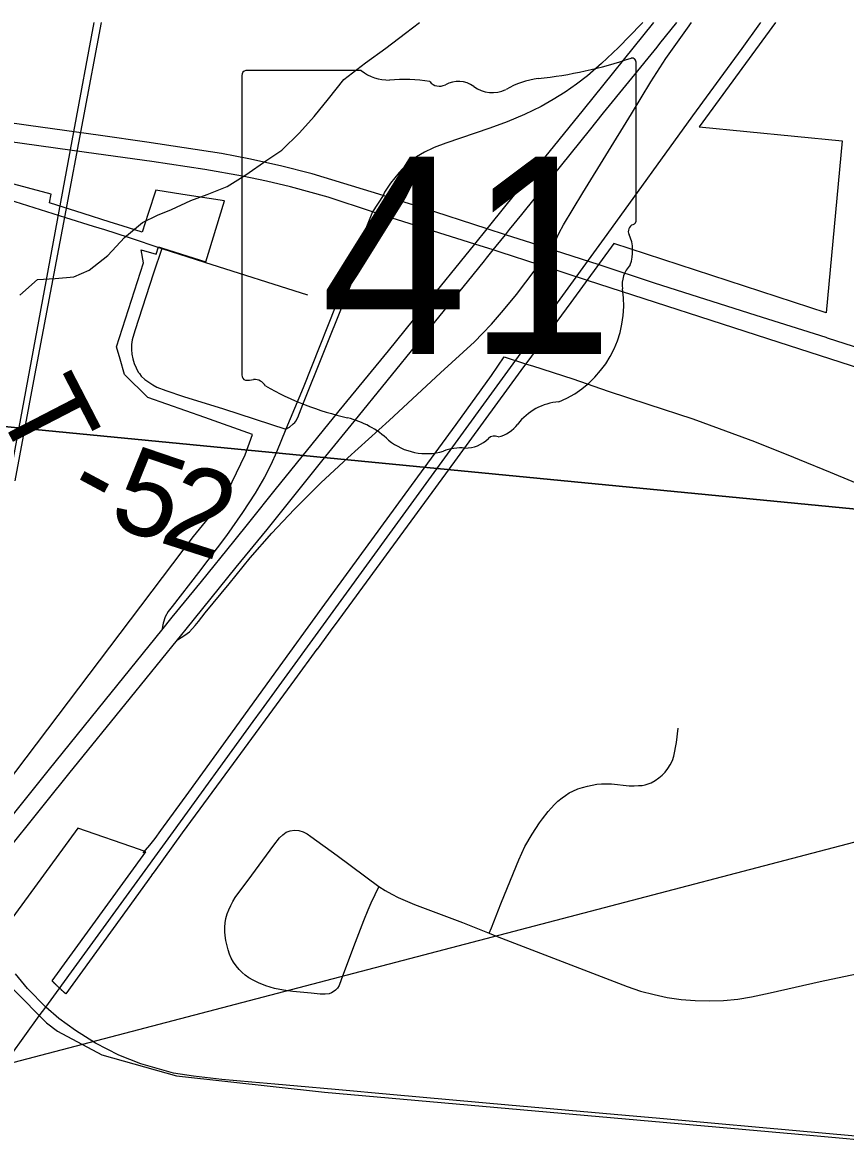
# Model space of a CAD drawing. Extents: x 0 to 34, y 0 to 22.
# Drawn here: x 7.471 to 8.022, y 20.207 to 20.958 of the extents above; entities that cross this region are included whole.
import ezdxf

# ---------------------------------------------------------------- set-up
doc = ezdxf.new("R2010")
doc.units = 0
for name, color, linetype in [('GM_X_City_Street', 7, 'Continuous'), ('GM_X_Corporation', 7, 'Continuous'), ('GM_X_Interchange_Ramps', 7, 'Continuous'), ('GM_X_Minor_River', 7, 'Continuous'), ('GM_X_Rail_Line', 7, 'Continuous'), ('GM_X_State_Location', 7, 'Continuous'), ('GM_X_State_Route', 7, 'Continuous'), ('GM_X_State_Shield', 7, 'Continuous'), ('GM_X_Township_Road', 7, 'Continuous'), ('GM_X_Township_Road_Text', 7, 'Continuous'), ('GM_X_US_Route', 7, 'Continuous'), ('SH_Text', 7, 'Continuous')]:
    doc.layers.add(name, color=color, linetype=linetype)

msp = doc.modelspace()

# ---------------------------------------------------------------- linework, layer by layer
at = {"layer": 'GM_X_City_Street'}
for points in [[(7.78356, 20.34885), (7.78502, 20.35254), (7.7914, 20.36865), (7.79975, 20.3893), (7.80337, 20.39798), (7.80737, 20.40679), (7.81218, 20.41515), (7.81462, 20.41893), (7.81711, 20.42264), (7.81915, 20.42534), (7.82296, 20.43021), (7.82493, 20.43244), (7.8271, 20.43501), (7.82947, 20.43711), (7.8323, 20.43941), (7.83451, 20.441), (7.8371, 20.4427), (7.83947, 20.44388), (7.84289, 20.44533), (7.84585, 20.44639), (7.8492, 20.44724), (7.85229, 20.44796), (7.85551, 20.44862), (7.85874, 20.44888), (7.86176, 20.44882), (7.86525, 20.44882), (7.87709, 20.4475), (7.8805, 20.44744), (7.8834, 20.44757), (7.88581, 20.44776), (7.88793, 20.44822), (7.88983, 20.44878), (7.89175, 20.44954), (7.89445, 20.45098), (7.89694, 20.4527), (7.89911, 20.45447), (7.90122, 20.45658), (7.90306, 20.45892), (7.90466, 20.46148), (7.90602, 20.46434), (7.90694, 20.46723), (7.90871, 20.4765), (7.9099, 20.48597)], [(7.70961, 20.38007), (7.70438, 20.36893), (7.70241, 20.36433), (7.69945, 20.35723), (7.69281, 20.33986), (7.68449, 20.31776), (7.68307, 20.31395), (7.68202, 20.31224), (7.68077, 20.31086), (7.67922, 20.30967), (7.678, 20.30903), (7.67643, 20.30843), (7.67387, 20.30817), (7.67038, 20.30824), (7.66433, 20.30876), (7.65212, 20.31001), (7.646, 20.31072), (7.64, 20.31198), (7.63407, 20.31373), (7.62915, 20.31573), (7.62559, 20.31751), (7.62276, 20.31915), (7.62034, 20.32086), (7.61823, 20.32263), (7.61626, 20.32474), (7.61422, 20.32718), (7.61257, 20.32947), (7.61093, 20.3323), (7.60975, 20.33493), (7.60889, 20.33783), (7.60738, 20.34394), (7.60692, 20.34736), (7.60672, 20.34984), (7.60665, 20.35287), (7.60688, 20.35587), (7.60743, 20.35885), (7.60825, 20.36176), (7.60932, 20.36461), (7.61059, 20.3674), (7.61204, 20.37009), (7.61366, 20.37267), (7.62473, 20.3877), (7.63955, 20.40777), (7.64331, 20.41265), (7.64542, 20.41472), (7.64781, 20.41636), (7.65049, 20.41742), (7.65334, 20.41781), (7.65622, 20.41755), (7.659, 20.41667), (7.66165, 20.41529), (7.66419, 20.4136), (7.68186, 20.40081), (7.70961, 20.38007)], [(7.70961, 20.38007), (7.71389, 20.37735), (7.71833, 20.37493), (7.72263, 20.37288), (7.7336, 20.36801), (7.76564, 20.35596), (7.78356, 20.34885), (7.78875, 20.34679), (7.84968, 20.32323), (7.8759, 20.31336), (7.8848, 20.31024), (7.89377, 20.30787), (7.90265, 20.306), (7.91183, 20.30462), (7.92139, 20.30392), (7.93067, 20.30363), (7.94024, 20.30383), (7.94971, 20.30481), (7.95888, 20.30639), (7.97145, 20.30907), (8.00483, 20.31659), (8.02919, 20.32164)]]:
    msp.add_lwpolyline(points, dxfattribs=at)
at = {"layer": 'GM_X_Corporation'}
for points in [[(8.11662, 20.95784), (8.08658, 20.62681), (7.08216, 20.72429), (7.10245, 20.95784)], [(7.97504, 20.95784), (7.9239, 20.88797), (8.01968, 20.8786), (8.00881, 20.76368), (7.86693, 20.8101), (7.83809, 20.77069), (7.81637, 20.74102), (7.81183, 20.73481), (7.80475, 20.72514), (7.75424, 20.65611), (7.7287, 20.62103), (7.68054, 20.55538), (7.67895, 20.5532), (7.66845, 20.53889), (7.66831, 20.53871), (7.65328, 20.51822), (7.60984, 20.45899), (7.57824, 20.41592), (7.55947, 20.39), (7.55774, 20.38761), (7.55773, 20.3876), (7.5413, 20.36498), (7.50024, 20.30844), (7.50011, 20.30855), (7.49997, 20.30867), (7.49984, 20.30879), (7.49971, 20.3089), (7.49957, 20.30902), (7.49944, 20.30914), (7.49931, 20.30926), (7.49918, 20.30938), (7.49904, 20.30949), (7.49891, 20.30961), (7.49878, 20.30973), (7.49865, 20.30985), (7.49851, 20.30997), (7.49838, 20.31009), (7.49825, 20.31021), (7.49812, 20.31033), (7.49799, 20.31044), (7.49786, 20.31056), (7.49772, 20.31068), (7.49759, 20.3108), (7.49746, 20.31092), (7.49733, 20.31104), (7.4972, 20.31116), (7.49711, 20.31124), (7.49694, 20.3114), (7.49681, 20.31152), (7.49668, 20.31165), (7.49655, 20.31177), (7.49642, 20.31189), (7.49629, 20.31201), (7.49616, 20.31213), (7.49603, 20.31225), (7.4959, 20.31237), (7.49577, 20.31249), (7.49564, 20.31262), (7.49551, 20.31274), (7.49538, 20.31286), (7.49525, 20.31298), (7.49513, 20.3131), (7.495, 20.31323), (7.49487, 20.31335), (7.49474, 20.31347), (7.49461, 20.31359), (7.49448, 20.31372), (7.49436, 20.31384), (7.49423, 20.31396), (7.4941, 20.31409), (7.49406, 20.31413), (7.49397, 20.31421), (7.49385, 20.31433), (7.49372, 20.31446), (7.49359, 20.31458), (7.49347, 20.31471), (7.49334, 20.31483), (7.49321, 20.31496), (7.49308, 20.31508), (7.49296, 20.3152), (7.49283, 20.31533), (7.49271, 20.31545), (7.49258, 20.31558), (7.49245, 20.3157), (7.49233, 20.31583), (7.4922, 20.31596), (7.49208, 20.31608), (7.49195, 20.31621), (7.49183, 20.31633), (7.4917, 20.31646), (7.49158, 20.31658), (7.49145, 20.31671), (7.49133, 20.31684), (7.4912, 20.31696), (7.49108, 20.31709), (7.55377, 20.40341), (7.54961, 20.40487), (7.50847, 20.41921), (7.46243, 20.35631)], [(7.45289, 20.43873), (7.58572, 20.61423), (7.60573, 20.63864), (7.62031, 20.66884), (7.6252, 20.68227), (7.59321, 20.69361), (7.55524, 20.70707), (7.53965, 20.72254), (7.53666, 20.73261), (7.5342, 20.74088), (7.55223, 20.79706), (7.55069, 20.80592), (7.56071, 20.80286), (7.56226, 20.80784), (7.56424, 20.80717), (7.59398, 20.79773), (7.59573, 20.80363), (7.60652, 20.83848), (7.57861, 20.84292), (7.56051, 20.8458), (7.5555, 20.83021), (7.55145, 20.81759), (7.53808, 20.82181), (7.53008, 20.82433), (7.51198, 20.83004), (7.4894, 20.83716), (7.49045, 20.84301), (7.49045, 20.84301), (7.39199, 20.86938)]]:
    msp.add_lwpolyline(points, dxfattribs=at)
msp.add_lwpolyline([(7.08216, 20.72429), (8.08658, 20.62681), (8.00052, 19.62676), (6.98964, 19.72208)], close=True, dxfattribs=at)
at = {"layer": 'GM_X_Interchange_Ramps'}
for points in [[(7.88631, 20.95784), (7.88524, 20.9567), (7.86993, 20.94121), (7.85866, 20.93048), (7.84931, 20.92227), (7.84199, 20.91649), (7.83435, 20.91115), (7.82641, 20.90624), (7.81823, 20.90176), (7.80702, 20.89636), (7.79557, 20.8915), (7.78392, 20.88714), (7.75443, 20.87725), (7.7467, 20.87422)], [(7.82467, 20.80619), (7.8262, 20.80851), (7.83037, 20.81711), (7.83321, 20.82263), (7.84605, 20.84392), (7.87873, 20.89682), (7.89153, 20.91815), (7.90174, 20.93376), (7.91605, 20.95414), (7.91879, 20.95784)], [(7.7467, 20.87422), (7.74573, 20.87384), (7.74014, 20.87114), (7.73482, 20.86794), (7.73228, 20.86615), (7.72755, 20.86213), (7.72325, 20.85763), (7.71742, 20.85034), (7.71349, 20.84434), (7.71257, 20.84209)], [(7.71257, 20.84209), (7.70551, 20.83124), (7.70097, 20.82018), (7.6865, 20.78258), (7.65897, 20.71349), (7.64755, 20.68592), (7.64128, 20.67051), (7.6374, 20.66206), (7.63315, 20.6538), (7.6269, 20.6431), (7.61847, 20.63009), (7.60775, 20.61489), (7.58913, 20.59011), (7.57137, 20.56738), (7.56882, 20.56403), (7.56676, 20.56042), (7.56534, 20.55616), (7.56462, 20.55158)], [(7.64755, 20.68592), (7.65, 20.68725), (7.65249, 20.68942), (7.65359, 20.69044), (7.65427, 20.69135), (7.65545, 20.69372), (7.65886, 20.70232), (7.67294, 20.73729), (7.69872, 20.80175), (7.70495, 20.81716), (7.70909, 20.82694), (7.71017, 20.82971)], [(7.81691, 20.79588), (7.82096, 20.80099), (7.82355, 20.80451), (7.82467, 20.80619)], [(7.77899, 20.74993), (7.78507, 20.75623), (7.79315, 20.76537), (7.80176, 20.77599), (7.81419, 20.79246), (7.81691, 20.79588)], [(7.57496, 20.54515), (7.57995, 20.54813), (7.58303, 20.55047), (7.58686, 20.55461), (7.58899, 20.55737), (7.59354, 20.56302), (7.6095, 20.58256), (7.62353, 20.59999), (7.63819, 20.61636), (7.65296, 20.63219), (7.67093, 20.64994), (7.689, 20.66674), (7.71652, 20.69181), (7.75095, 20.7236), (7.77358, 20.74433), (7.77899, 20.74993)]]:
    msp.add_lwpolyline(points, dxfattribs=at)
at = {"layer": 'GM_X_Minor_River'}
msp.add_lwpolyline([(7.46958, 20.77547), (7.48139, 20.78601), (7.49312, 20.78668), (7.50561, 20.78773), (7.51586, 20.79221), (7.52842, 20.80198), (7.53949, 20.81405), (7.55167, 20.8242), (7.56154, 20.82906), (7.57103, 20.83279), (7.58394, 20.83876), (7.59494, 20.84286), (7.60822, 20.84807), (7.62076, 20.85594), (7.63484, 20.86571), (7.64473, 20.87247), (7.65654, 20.88414), (7.66646, 20.89508), (7.67601, 20.90677), (7.68633, 20.9196), (7.70079, 20.93087), (7.71448, 20.94064), (7.72742, 20.95079), (7.73679, 20.95784)], dxfattribs=at)
at = {"layer": 'GM_X_Rail_Line'}
for points in [[(7.51897, 20.95784), (7.5055, 20.88474), (7.44147, 20.53994), (7.4238, 20.45147), (7.42156, 20.40248), (7.43115, 20.36454), (7.45915, 20.31775), (7.48232, 20.29421)], [(7.46651, 20.65131), (7.47895, 20.71815), (7.48703, 20.76062), (7.49964, 20.82769), (7.52408, 20.95784)], [(7.48694, 20.29949), (7.57229, 20.41699), (7.62563, 20.49046), (7.63117, 20.49804), (7.72066, 20.62109), (7.86237, 20.8161), (7.91983, 20.89536), (7.9405, 20.92369), (7.95265, 20.94046), (7.96452, 20.95687), (7.96523, 20.95784)], [(8.11104, 20.20593), (8.0828, 20.20842), (8.05089, 20.21113), (7.96406, 20.21905), (7.93438, 20.22168), (7.89763, 20.22503), (7.8746, 20.22707), (7.79643, 20.23387), (7.71949, 20.24089), (7.68055, 20.24438), (7.65521, 20.24672), (7.64002, 20.24795), (7.62468, 20.24921), (7.60472, 20.25118), (7.58567, 20.25323), (7.57229, 20.25534), (7.55052, 20.26159), (7.5357, 20.26734), (7.52017, 20.27544), (7.50679, 20.28377), (7.49576, 20.29186), (7.48694, 20.29949), (7.4747, 20.31195), (7.46671, 20.32172)], [(7.4536, 20.25349), (7.48255, 20.29368), (7.48694, 20.29949)], [(7.48232, 20.29421), (7.48749, 20.28896), (7.49472, 20.2834), (7.52452, 20.26748), (7.57443, 20.25347), (7.67337, 20.24253), (7.99809, 20.21388), (8.15925, 20.19925), (8.24374, 20.18913), (8.60421, 20.11965), (8.71999, 20.10062), (8.77096, 20.10215), (8.84859, 20.10474), (8.84939, 20.10462)]]:
    msp.add_lwpolyline(points, dxfattribs=at)
at = {"layer": 'GM_X_State_Route'}
for points in [[(7.962, 20.76198), (7.89404, 20.78353), (7.85705, 20.79574), (7.8271, 20.80541), (7.82467, 20.80619), (7.79439, 20.81596), (7.78215, 20.81991), (7.73818, 20.83409), (7.71637, 20.8409), (7.71257, 20.84209), (7.66507, 20.85653), (7.64403, 20.862), (7.62282, 20.86674), (7.60452, 20.8702), (7.5546, 20.87776), (7.52353, 20.8823), (7.47531, 20.88902), (7.41986, 20.89665)], [(7.81691, 20.79588), (7.79091, 20.80436), (7.78621, 20.80584), (7.77387, 20.80971), (7.71017, 20.82971), (7.70953, 20.82992), (7.70685, 20.8308), (7.70551, 20.83124), (7.6757, 20.84098), (7.6505, 20.84787), (7.63455, 20.85173), (7.6186, 20.85509), (7.59323, 20.85945), (7.55796, 20.86483), (7.51412, 20.87087), (7.46155, 20.87826)], [(8.07216, 20.7137), (8.03899, 20.72408), (7.97751, 20.74392), (7.84934, 20.78529), (7.81995, 20.79488), (7.81691, 20.79588)], [(8.00982, 20.7468), (8.0089, 20.7471), (7.962, 20.76198)], [(8.0751, 20.72589), (8.06255, 20.7298), (8.02729, 20.74124), (8.00982, 20.7468)]]:
    msp.add_lwpolyline(points, dxfattribs=at)
at = {"layer": 'GM_X_State_Shield'}
for p, q in [((7.88178, 20.82601), (7.88178, 20.93069)), ((7.61812, 20.92229), (7.61812, 20.72217)), ((7.69793, 20.92574), (7.62071, 20.92574)), ((7.88176, 20.82604), (7.88178, 20.82601))]:
    msp.add_line(p, q, dxfattribs=at)
for centre, radius, start, end in [((7.78786, 21.19857), 0.27962, 275.84447, 288.90645), ((7.87886, 20.93113), 0.00294, 351.86209, 97.738), ((7.62114, 20.92272), 0.00305, 98.1301, 188.1301), ((7.71632, 20.94897), 0.02963, 231.61951, 271.11188), ((7.82353, 20.86461), 0.05625, 97.34618, 120.76885), ((7.72614, 20.81339), 0.10636, 80.48669, 94.98827), ((7.75029, 20.92376), 0.00855, 219.79206, 297.10237), ((7.76284, 20.90063), 0.01777, 54.46668, 119.14113), ((7.78577, 20.93235), 0.02138, 233.85621, 294.82819), ((7.8811, 20.81832), 0.00454, 107.94398, 210.33697), ((7.87865, 20.82561), 0.00314, 289.60381, 7.73413), ((7.85221, 20.80509), 0.02727, 340.03296, 23.64957), ((7.8923, 20.7822), 0.01984, 136.8065, 186.92959), ((7.80352, 20.76888), 0.06994, 292.30889, 8.98584), ((7.62116, 20.72173), 0.00308, 171.95839, 258.30661), ((7.62163, 20.74221), 0.02352, 267.33899, 280.60386), ((7.62644, 20.71063), 0.00848, 29.74838, 93.27175), ((7.7335, 20.89043), 0.20192, 240.41292, 257.1985), ((7.83301, 20.66599), 0.0383, 94.40312, 142.57675), ((7.6733, 20.63227), 0.06318, 47.18416, 75.83597), ((7.78448, 20.70278), 0.0226, 282.87319, 323.27711), ((7.78705, 20.67527), 0.00601, 65.75173, 132.64842), ((7.74163, 20.70963), 0.04009, 230.70037, 286.29184), ((7.7648, 20.64044), 0.03294, 85.69512, 111.20995), ((7.76773, 20.69465), 0.02136, 268.77702, 315.54927)]:
    msp.add_arc(centre, radius, start, end, dxfattribs=at)
at = {"layer": 'GM_X_Township_Road'}
for p, q in [((7.56447, 20.80664), (7.59312, 20.79755)), ((7.59312, 20.79755), (7.66187, 20.77572))]:
    msp.add_line(p, q, dxfattribs=at)
for points in [[(7.4174, 20.85338), (7.44408, 20.84508), (7.44473, 20.84487), (7.50016, 20.82753), (7.51866, 20.82171), (7.52617, 20.81931), (7.54209, 20.8142), (7.56447, 20.80664)], [(7.56447, 20.80664), (7.55898, 20.79019), (7.54642, 20.75174), (7.54481, 20.74562), (7.54432, 20.74246), (7.54418, 20.73924), (7.54443, 20.73602), (7.54507, 20.73286), (7.54603, 20.7298), (7.54728, 20.72685), (7.54882, 20.72402), (7.54951, 20.72309), (7.55078, 20.72139), (7.55316, 20.71919), (7.55574, 20.71727), (7.55843, 20.71559), (7.56125, 20.71409), (7.56711, 20.71173), (7.57899, 20.70784), (7.60576, 20.69949), (7.64755, 20.68592)], [(7.55202, 20.4027), (7.55662, 20.40782), (7.56017, 20.41223), (7.56395, 20.41768), (7.58254, 20.44331), (7.61365, 20.48589), (7.64075, 20.5237), (7.67169, 20.5664), (7.73582, 20.65399), (7.76152, 20.68899), (7.78497, 20.72181), (7.79363, 20.73427)], [(7.79363, 20.73427), (7.80704, 20.72993), (7.80852, 20.72945), (7.81238, 20.7282)], [(7.81238, 20.7282), (7.83939, 20.71947), (7.86299, 20.7113), (7.88971, 20.7027), (7.91962, 20.6929), (7.93731, 20.68646), (7.96106, 20.67765), (7.98703, 20.66712), (7.99085, 20.66554), (8.01169, 20.65713), (8.03783, 20.64625)]]:
    msp.add_lwpolyline(points, dxfattribs=at)
at = {"layer": 'GM_X_US_Route'}
for p, q in [((7.73741, 20.74553), (7.77273, 20.78918)), ((7.45442, 20.39587), (7.48776, 20.43741))]:
    msp.add_line(p, q, dxfattribs=at)
for points in [[(7.56462, 20.55158), (7.57151, 20.56015), (7.59111, 20.58407), (7.61275, 20.61076), (7.62371, 20.62436), (7.64046, 20.64534), (7.68325, 20.69821), (7.71615, 20.73826), (7.73837, 20.76597), (7.77387, 20.80971), (7.78215, 20.81991), (7.79488, 20.83561), (7.84652, 20.89952), (7.89362, 20.95784)], [(7.89583, 20.94139), (7.89775, 20.94374), (7.90903, 20.95784)], [(7.85062, 20.88568), (7.86007, 20.8974), (7.89583, 20.94139)], [(7.8053, 20.82944), (7.80718, 20.83178), (7.85062, 20.88568)], [(7.7881, 20.80818), (7.79439, 20.81596), (7.79712, 20.81933), (7.8053, 20.82944)], [(7.78161, 20.80015), (7.78621, 20.80584), (7.7881, 20.80818)], [(7.77273, 20.78918), (7.78029, 20.79853), (7.78161, 20.80015)], [(7.48776, 20.43741), (7.50223, 20.45545), (7.54366, 20.50622), (7.57496, 20.54515), (7.58075, 20.55225), (7.61429, 20.59354), (7.63491, 20.61882), (7.67417, 20.66781), (7.69327, 20.69098), (7.73741, 20.74553)], [(7.37884, 20.32145), (7.38136, 20.32457), (7.40693, 20.35632), (7.42696, 20.38012), (7.44912, 20.40834), (7.46084, 20.42295), (7.48931, 20.4586), (7.53076, 20.50952), (7.56462, 20.55158)]]:
    msp.add_lwpolyline(points, dxfattribs=at)
at = {"layer": 'SH_Text'}
msp.add_lwpolyline([(9.4782, 20.78964), (4.28936, 19.4307), (9.4782, 20.42968)], close=True, dxfattribs=at)

# ---------------------------------------------------------------- texts
at = {"layer": 'GM_X_State_Location'}
for s, p in [('s', (7.74698, 20.80893)), ('r', (7.74697, 20.80893))]:
    msp.add_text(s, height=0.000189, dxfattribs=at).set_placement(p)
msp.add_text('41', height=0.000189, rotation=0.00001, dxfattribs=at).set_placement((7.69929, 20.79515))
at = {"layer": 'GM_X_State_Shield'}
msp.add_text('41', height=0.131836, dxfattribs=at).set_placement((7.67083, 20.73628))
at = {"layer": 'GM_X_Township_Road_Text'}
for s, rotation, p in [('T', 297.33511, (7.4527, 20.70112)), ('5', 341.17961, (7.52761, 20.62232)), ('-', 331.8178, (7.49795, 20.63728)), ('2', 342.27869, (7.56161, 20.61075))]:
    msp.add_text(s, height=0.05682, rotation=rotation, dxfattribs=at).set_placement(p)

doc.saveas('drawing.dxf')
